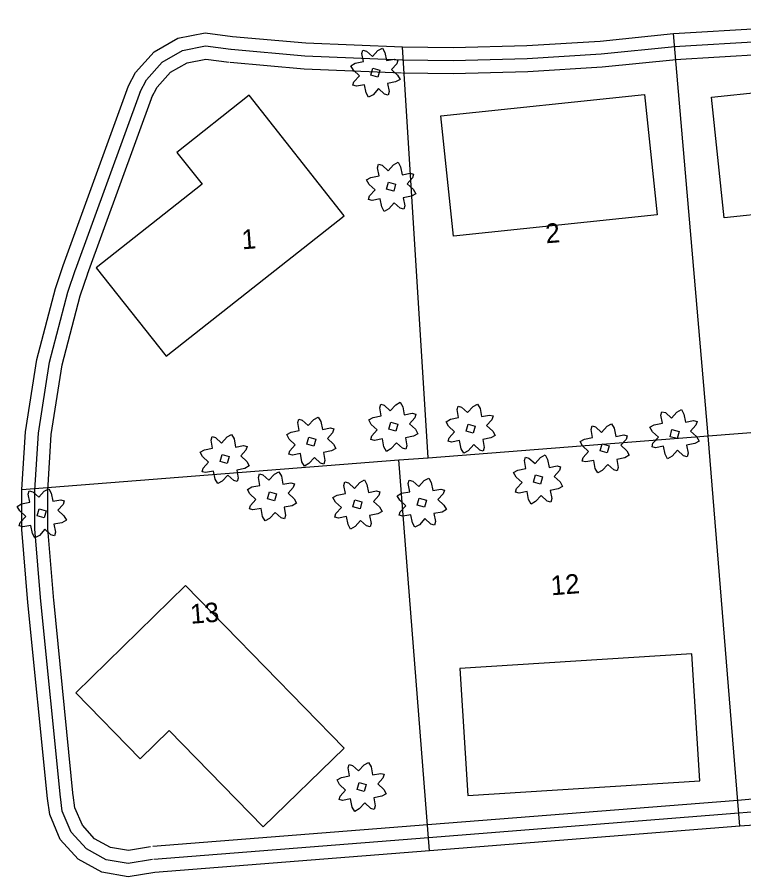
# Model space of a CAD drawing. Extents: x 1810019 to 1811399, y 1074962 to 1076105.
# Drawn here: x 1810018.7 to 1810242.7, y 1074961.5 to 1075226.6 of the extents above; entities that cross this region are included whole.
import ezdxf

# ---------------------------------------------------------------- set-up
doc = ezdxf.new("R2010")
doc.units = 0
for name, color, linetype in [('Environmental-New trees', 7, 'Continuous'), ('Property-Buildings', 7, 'Continuous'), ('Roadway-Land lines', 7, 'Continuous'), ('Roadway-Sidewalks', 7, 'Continuous'), ('Text-Property owner', 7, 'Continuous')]:
    doc.layers.add(name, color=color, linetype=linetype)

msp = doc.modelspace()

# ---------------------------------------------------------------- linework, layer by layer
at = {"layer": 'Environmental-New trees'}
for points in [[(1810122.18, 1075205.63), (1810122.48, 1075206.72), (1810124.18, 1075208.58), (1810122.32, 1075210.27), (1810121.54, 1075211.66), (1810122.89, 1075212.42), (1810125.4, 1075212.91), (1810124.92, 1075215.38), (1810125.23, 1075216.46), (1810126.31, 1075216.16), (1810128.17, 1075214.47), (1810129.87, 1075216.33), (1810131.26, 1075217.1), (1810132.03, 1075215.72), (1810132.51, 1075213.24), (1810134.98, 1075213.72), (1810136.06, 1075213.41), (1810135.69, 1075212.26), (1810134.06, 1075210.47), (1810135.92, 1075208.77), (1810136.7, 1075207.39), (1810135.35, 1075206.63), (1810132.84, 1075206.14), (1810133.31, 1075203.66), (1810133.01, 1075202.58), (1810131.93, 1075202.89), (1810130.06, 1075204.58), (1810128.37, 1075202.72), (1810126.98, 1075201.94), (1810126.21, 1075203.33), (1810125.73, 1075205.8), (1810123.26, 1075205.33)], [(1810128.34, 1075210.91), (1810130.51, 1075210.3), (1810129.9, 1075208.13), (1810127.73, 1075208.74)], [(1810127.02, 1075170.43), (1810127.33, 1075171.52), (1810129.02, 1075173.38), (1810127.16, 1075175.07), (1810126.38, 1075176.46), (1810127.73, 1075177.22), (1810130.24, 1075177.71), (1810129.77, 1075180.18), (1810130.07, 1075181.26), (1810131.16, 1075180.96), (1810133.02, 1075179.26), (1810134.71, 1075181.13), (1810136.1, 1075181.9), (1810136.88, 1075180.52), (1810137.35, 1075178.04), (1810139.82, 1075178.52), (1810140.9, 1075178.21), (1810140.53, 1075177.06), (1810138.9, 1075175.27), (1810140.77, 1075173.57), (1810141.54, 1075172.19), (1810140.19, 1075171.43), (1810137.68, 1075170.94), (1810138.16, 1075168.46), (1810137.85, 1075167.38), (1810136.77, 1075167.69), (1810134.91, 1075169.38), (1810133.21, 1075167.52), (1810131.83, 1075166.74), (1810131.05, 1075168.13), (1810130.57, 1075170.6), (1810128.1, 1075170.13)], [(1810133.18, 1075175.71), (1810135.35, 1075175.1), (1810134.74, 1075172.93), (1810132.57, 1075173.54)], [(1810127.69, 1075096.42), (1810128, 1075097.5), (1810129.69, 1075099.36), (1810127.83, 1075101.06), (1810127.05, 1075102.45), (1810128.4, 1075103.2), (1810130.91, 1075103.7), (1810130.44, 1075106.17), (1810130.74, 1075107.25), (1810131.83, 1075106.95), (1810133.69, 1075105.25), (1810135.38, 1075107.11), (1810136.77, 1075107.89), (1810137.55, 1075106.5), (1810138.02, 1075104.03), (1810140.49, 1075104.5), (1810141.58, 1075104.2), (1810141.21, 1075103.04), (1810139.58, 1075101.25), (1810141.44, 1075099.56), (1810142.22, 1075098.17), (1810140.86, 1075097.42), (1810138.36, 1075096.92), (1810138.83, 1075094.45), (1810138.52, 1075093.37), (1810137.44, 1075093.67), (1810135.58, 1075095.37), (1810133.89, 1075093.51), (1810132.5, 1075092.73), (1810131.72, 1075094.12), (1810131.25, 1075096.59), (1810128.78, 1075096.11)], [(1810151.52, 1075095.86), (1810151.82, 1075096.94), (1810153.52, 1075098.8), (1810151.66, 1075100.5), (1810150.88, 1075101.88), (1810152.23, 1075102.64), (1810154.74, 1075103.14), (1810154.27, 1075105.61), (1810154.57, 1075106.69), (1810155.65, 1075106.38), (1810157.51, 1075104.69), (1810159.21, 1075106.55), (1810160.6, 1075107.33), (1810161.37, 1075105.94), (1810161.85, 1075103.47), (1810164.32, 1075103.94), (1810165.4, 1075103.64), (1810165.03, 1075102.48), (1810163.4, 1075100.69), (1810165.26, 1075099), (1810166.04, 1075097.61), (1810164.69, 1075096.85), (1810162.18, 1075096.36), (1810162.65, 1075093.89), (1810162.35, 1075092.81), (1810161.27, 1075093.11), (1810159.41, 1075094.81), (1810157.71, 1075092.94), (1810156.32, 1075092.17), (1810155.55, 1075093.56), (1810155.07, 1075096.03), (1810152.6, 1075095.55)], [(1810214.38, 1075094.14), (1810214.68, 1075095.23), (1810216.38, 1075097.09), (1810214.52, 1075098.78), (1810213.74, 1075100.17), (1810215.09, 1075100.93), (1810217.6, 1075101.42), (1810217.13, 1075103.89), (1810217.43, 1075104.97), (1810218.51, 1075104.67), (1810220.37, 1075102.98), (1810222.07, 1075104.84), (1810223.46, 1075105.62), (1810224.23, 1075104.23), (1810224.71, 1075101.76), (1810227.18, 1075102.23), (1810228.26, 1075101.92), (1810227.89, 1075100.77), (1810226.26, 1075098.98), (1810228.12, 1075097.29), (1810228.9, 1075095.9), (1810227.55, 1075095.14), (1810225.04, 1075094.65), (1810225.51, 1075092.18), (1810225.21, 1075091.09), (1810224.13, 1075091.4), (1810222.27, 1075093.09), (1810220.57, 1075091.23), (1810219.18, 1075090.45), (1810218.41, 1075091.84), (1810217.93, 1075094.31), (1810215.46, 1075093.84)], [(1810102.42, 1075091.85), (1810102.73, 1075092.93), (1810104.42, 1075094.79), (1810102.56, 1075096.49), (1810101.78, 1075097.88), (1810103.13, 1075098.63), (1810105.64, 1075099.13), (1810105.17, 1075101.6), (1810105.47, 1075102.68), (1810106.56, 1075102.38), (1810108.42, 1075100.68), (1810110.11, 1075102.54), (1810111.5, 1075103.32), (1810112.28, 1075101.93), (1810112.75, 1075099.46), (1810115.22, 1075099.94), (1810116.3, 1075099.63), (1810115.93, 1075098.47), (1810114.31, 1075096.69), (1810116.17, 1075094.99), (1810116.94, 1075093.6), (1810115.59, 1075092.85), (1810113.08, 1075092.35), (1810113.56, 1075089.88), (1810113.25, 1075088.8), (1810112.17, 1075089.1), (1810110.31, 1075090.8), (1810108.61, 1075088.94), (1810107.23, 1075088.16), (1810106.45, 1075089.55), (1810105.98, 1075092.02), (1810103.5, 1075091.55)], [(1810133.86, 1075101.7), (1810136.02, 1075101.09), (1810135.41, 1075098.92), (1810133.25, 1075099.53)], [(1810157.68, 1075101.14), (1810159.85, 1075100.53), (1810159.24, 1075098.36), (1810157.07, 1075098.97)], [(1810192.85, 1075089.75), (1810193.15, 1075090.83), (1810194.85, 1075092.7), (1810192.98, 1075094.39), (1810192.21, 1075095.78), (1810193.56, 1075096.54), (1810196.07, 1075097.03), (1810195.59, 1075099.5), (1810195.9, 1075100.58), (1810196.98, 1075100.28), (1810198.84, 1075098.58), (1810200.54, 1075100.45), (1810201.92, 1075101.22), (1810202.7, 1075099.84), (1810203.18, 1075097.36), (1810205.65, 1075097.84), (1810206.73, 1075097.53), (1810206.36, 1075096.38), (1810204.73, 1075094.59), (1810206.59, 1075092.89), (1810207.37, 1075091.51), (1810206.02, 1075090.75), (1810203.51, 1075090.25), (1810203.98, 1075087.78), (1810203.68, 1075086.7), (1810202.59, 1075087.01), (1810200.73, 1075088.7), (1810199.04, 1075086.84), (1810197.65, 1075086.06), (1810196.87, 1075087.45), (1810196.4, 1075089.92), (1810193.93, 1075089.45)], [(1810220.54, 1075099.42), (1810222.71, 1075098.81), (1810222.1, 1075096.65), (1810219.93, 1075097.26)], [(1810075.69, 1075086.46), (1810075.99, 1075087.55), (1810077.69, 1075089.41), (1810075.83, 1075091.1), (1810075.05, 1075092.49), (1810076.4, 1075093.25), (1810078.91, 1075093.74), (1810078.44, 1075096.21), (1810078.74, 1075097.29), (1810079.82, 1075096.99), (1810081.68, 1075095.3), (1810083.38, 1075097.16), (1810084.77, 1075097.93), (1810085.54, 1075096.55), (1810086.02, 1075094.07), (1810088.49, 1075094.55), (1810089.57, 1075094.24), (1810089.2, 1075093.09), (1810087.57, 1075091.3), (1810089.43, 1075089.6), (1810090.21, 1075088.22), (1810088.86, 1075087.46), (1810086.35, 1075086.97), (1810086.83, 1075084.49), (1810086.52, 1075083.41), (1810085.44, 1075083.72), (1810083.58, 1075085.41), (1810081.88, 1075083.55), (1810080.49, 1075082.77), (1810079.72, 1075084.16), (1810079.24, 1075086.63), (1810076.77, 1075086.16)], [(1810108.58, 1075097.13), (1810110.75, 1075096.52), (1810110.14, 1075094.35), (1810107.97, 1075094.96)], [(1810199.01, 1075095.03), (1810201.18, 1075094.42), (1810200.57, 1075092.25), (1810198.4, 1075092.86)], [(1810081.85, 1075091.74), (1810084.02, 1075091.13), (1810083.41, 1075088.96), (1810081.24, 1075089.57)], [(1810172.31, 1075080.16), (1810172.61, 1075081.24), (1810174.31, 1075083.1), (1810172.45, 1075084.8), (1810171.67, 1075086.18), (1810173.02, 1075086.94), (1810175.53, 1075087.43), (1810175.06, 1075089.91), (1810175.36, 1075090.99), (1810176.44, 1075090.68), (1810178.31, 1075088.99), (1810180, 1075090.85), (1810181.39, 1075091.63), (1810182.16, 1075090.24), (1810182.64, 1075087.77), (1810185.11, 1075088.24), (1810186.19, 1075087.94), (1810185.82, 1075086.78), (1810184.19, 1075084.99), (1810186.05, 1075083.3), (1810186.83, 1075081.91), (1810185.48, 1075081.15), (1810182.97, 1075080.66), (1810183.45, 1075078.19), (1810183.14, 1075077.11), (1810182.06, 1075077.41), (1810180.2, 1075079.11), (1810178.5, 1075077.24), (1810177.11, 1075076.47), (1810176.34, 1075077.85), (1810175.86, 1075080.33), (1810173.39, 1075079.85)], [(1810090.28, 1075074.97), (1810090.59, 1075076.05), (1810092.28, 1075077.91), (1810090.42, 1075079.61), (1810089.64, 1075080.99), (1810091, 1075081.75), (1810093.5, 1075082.24), (1810093.03, 1075084.72), (1810093.34, 1075085.8), (1810094.42, 1075085.49), (1810096.28, 1075083.8), (1810097.97, 1075085.66), (1810099.36, 1075086.44), (1810100.14, 1075085.05), (1810100.61, 1075082.58), (1810103.08, 1075083.05), (1810104.17, 1075082.75), (1810103.8, 1075081.59), (1810102.17, 1075079.8), (1810104.03, 1075078.11), (1810104.81, 1075076.72), (1810103.46, 1075075.96), (1810100.95, 1075075.47), (1810101.42, 1075073), (1810101.12, 1075071.92), (1810100.03, 1075072.22), (1810098.17, 1075073.92), (1810096.48, 1075072.05), (1810095.09, 1075071.28), (1810094.31, 1075072.66), (1810093.84, 1075075.14), (1810091.37, 1075074.66)], [(1810116.64, 1075072.47), (1810116.94, 1075073.55), (1810118.64, 1075075.41), (1810116.78, 1075077.1), (1810116, 1075078.49), (1810117.35, 1075079.25), (1810119.86, 1075079.74), (1810119.39, 1075082.21), (1810119.69, 1075083.3), (1810120.77, 1075082.99), (1810122.63, 1075081.3), (1810124.33, 1075083.16), (1810125.72, 1075083.94), (1810126.49, 1075082.55), (1810126.97, 1075080.08), (1810129.44, 1075080.55), (1810130.52, 1075080.24), (1810130.15, 1075079.09), (1810128.52, 1075077.3), (1810130.38, 1075075.61), (1810131.16, 1075074.22), (1810129.81, 1075073.46), (1810127.3, 1075072.97), (1810127.77, 1075070.5), (1810127.47, 1075069.41), (1810126.39, 1075069.72), (1810124.53, 1075071.41), (1810122.83, 1075069.55), (1810121.44, 1075068.77), (1810120.67, 1075070.16), (1810120.19, 1075072.63), (1810117.72, 1075072.16)], [(1810136.48, 1075073.03), (1810136.78, 1075074.11), (1810138.48, 1075075.97), (1810136.61, 1075077.67), (1810135.84, 1075079.05), (1810137.19, 1075079.81), (1810139.7, 1075080.3), (1810139.22, 1075082.78), (1810139.53, 1075083.86), (1810140.61, 1075083.55), (1810142.47, 1075081.86), (1810144.17, 1075083.72), (1810145.55, 1075084.5), (1810146.33, 1075083.11), (1810146.8, 1075080.64), (1810149.28, 1075081.11), (1810150.36, 1075080.81), (1810149.99, 1075079.65), (1810148.36, 1075077.86), (1810150.22, 1075076.17), (1810151, 1075074.78), (1810149.65, 1075074.02), (1810147.14, 1075073.53), (1810147.61, 1075071.06), (1810147.31, 1075069.98), (1810146.22, 1075070.28), (1810144.36, 1075071.98), (1810142.67, 1075070.11), (1810141.28, 1075069.34), (1810140.5, 1075070.72), (1810140.03, 1075073.2), (1810137.56, 1075072.72)], [(1810178.47, 1075085.44), (1810180.64, 1075084.83), (1810180.03, 1075082.66), (1810177.86, 1075083.27)], [(1810019.32, 1075069.74), (1810019.62, 1075070.82), (1810021.32, 1075072.68), (1810019.46, 1075074.38), (1810018.68, 1075075.76), (1810020.03, 1075076.52), (1810022.54, 1075077.02), (1810022.07, 1075079.49), (1810022.37, 1075080.57), (1810023.45, 1075080.27), (1810025.31, 1075078.57), (1810027.01, 1075080.43), (1810028.4, 1075081.21), (1810029.17, 1075079.82), (1810029.65, 1075077.35), (1810032.12, 1075077.82), (1810033.2, 1075077.52), (1810032.83, 1075076.36), (1810031.2, 1075074.57), (1810033.06, 1075072.88), (1810033.84, 1075071.49), (1810032.49, 1075070.74), (1810029.98, 1075070.24), (1810030.45, 1075067.77), (1810030.15, 1075066.69), (1810029.07, 1075066.99), (1810027.21, 1075068.69), (1810025.51, 1075066.83), (1810024.12, 1075066.05), (1810023.35, 1075067.44), (1810022.87, 1075069.91), (1810020.4, 1075069.43)], [(1810096.45, 1075080.25), (1810098.61, 1075079.64), (1810098, 1075077.47), (1810095.84, 1075078.08)], [(1810122.8, 1075077.74), (1810124.97, 1075077.13), (1810124.36, 1075074.97), (1810122.19, 1075075.58)], [(1810142.64, 1075078.31), (1810144.81, 1075077.7), (1810144.2, 1075075.53), (1810142.03, 1075076.14)], [(1810025.48, 1075075.02), (1810027.65, 1075074.41), (1810027.04, 1075072.24), (1810024.87, 1075072.85)], [(1810117.93, 1074985.36), (1810118.23, 1074986.44), (1810119.93, 1074988.3), (1810118.06, 1074990), (1810117.29, 1074991.39), (1810118.64, 1074992.14), (1810121.15, 1074992.64), (1810120.67, 1074995.11), (1810120.98, 1074996.19), (1810122.06, 1074995.89), (1810123.92, 1074994.19), (1810125.62, 1074996.05), (1810127, 1074996.83), (1810127.78, 1074995.44), (1810128.26, 1074992.97), (1810130.73, 1074993.44), (1810131.81, 1074993.14), (1810131.44, 1074991.98), (1810129.81, 1074990.19), (1810131.67, 1074988.5), (1810132.45, 1074987.11), (1810131.1, 1074986.36), (1810128.59, 1074985.86), (1810129.06, 1074983.39), (1810128.76, 1074982.31), (1810127.68, 1074982.61), (1810125.81, 1074984.31), (1810124.12, 1074982.45), (1810122.73, 1074981.67), (1810121.95, 1074983.06), (1810121.48, 1074985.53), (1810119.01, 1074985.05)], [(1810124.09, 1074990.64), (1810126.26, 1074990.03), (1810125.65, 1074987.86), (1810123.48, 1074988.47)]]:
    msp.add_lwpolyline(points, close=True, dxfattribs=at)
at = {"layer": 'Property-Buildings'}
for points in [[(1810232.74, 1075201.92), (1810295.57, 1075208.5), (1810299.46, 1075171.37), (1810236.63, 1075164.79)], [(1810064.6, 1075122.04), (1810119.5, 1075165.36), (1810090.18, 1075202.53), (1810067.88, 1075184.93), (1810075.65, 1075175.09), (1810043.04, 1075149.36)], [(1810149.28, 1075196.19), (1810212.11, 1075202.77), (1810216, 1075165.65), (1810153.17, 1075159.06)], [(1810119.44, 1075001.25), (1810070.61, 1075051.32), (1810036.71, 1075018.26), (1810056.54, 1074997.93), (1810065.52, 1075006.68), (1810094.52, 1074976.95)], [(1810157.61, 1074986.59), (1810229.12, 1074991.12), (1810226.63, 1075030.3), (1810155.12, 1075025.76)]]:
    msp.add_lwpolyline(points, close=True, dxfattribs=at)
at = {"layer": 'Roadway-Land lines'}
for p, q in [((1810220.99, 1075221.55), (1810306.17, 1075226.61)), ((1810231.65, 1075097.52), (1810220.99, 1075221.55)), ((1810145.37, 1075090.78), (1810137.51, 1075217.47)), ((1810032.85, 1075150.09), (1810053, 1075205.4)), ((1810231.65, 1075097.52), (1810315.51, 1075104.07)), ((1810145.37, 1075090.78), (1810231.65, 1075097.52)), ((1810241.42, 1074977.13), (1810231.65, 1075097.52)), ((1810020.12, 1075081.01), (1810136.35, 1075090.08)), ((1810136.35, 1075090.08), (1810145.37, 1075090.78)), ((1810145.76, 1074969.58), (1810136.35, 1075090.08)), ((1810028.02, 1074985.66), (1810022, 1075046.13)), ((1810328.22, 1074983.99), (1810241.42, 1074977.13)), ((1810241.42, 1074977.13), (1810145.76, 1074969.58)), ((1810145.76, 1074969.58), (1810061.09, 1074962.89))]:
    msp.add_line(p, q, dxfattribs=at)
for points in [[(1810053, 1075205.4), (1810055.19, 1075209.6), (1810060.86, 1075215.93), (1810068.25, 1075220.14), (1810076.59, 1075221.79), (1810085.03, 1075220.71)], [(1810137.51, 1075217.47), (1810153.03, 1075217.28), (1810175.74, 1075217.84), (1810198.4, 1075219.27), (1810220.99, 1075221.55)], [(1810085.03, 1075220.71), (1810107.65, 1075218.71), (1810137.51, 1075217.47)], [(1810020.12, 1075081.01), (1810021.22, 1075098.76), (1810024.71, 1075121.09), (1810030.45, 1075142.95), (1810032.85, 1075150.09)], [(1810022, 1075046.13), (1810020.14, 1075068.65), (1810020.12, 1075081.01)], [(1810061.09, 1074962.89), (1810052.91, 1074961.53), (1810044.74, 1074962.93), (1810037.48, 1074966.93), (1810031.92, 1074973.08), (1810028.69, 1074980.71), (1810028.02, 1074985.66)]]:
    msp.add_lwpolyline(points, dxfattribs=at)
at = {"layer": 'Roadway-Sidewalks'}
for p, q in [((1810221.23, 1075217.56), (1810306.41, 1075222.62)), ((1810221.47, 1075213.56), (1810306.65, 1075218.63)), ((1810036.61, 1075148.72), (1810056.76, 1075204.03)), ((1810040.37, 1075147.35), (1810060.51, 1075202.66)), ((1810032, 1074986.05), (1810025.98, 1075046.52)), ((1810035.98, 1074986.45), (1810029.97, 1075046.92)), ((1810327.59, 1074991.96), (1810240.79, 1074985.11)), ((1810327.91, 1074987.98), (1810241.1, 1074981.12)), ((1810240.79, 1074985.11), (1810145.13, 1074977.55)), ((1810241.1, 1074981.12), (1810145.44, 1074973.56)), ((1810145.13, 1074977.55), (1810060.46, 1074970.86)), ((1810145.44, 1074973.56), (1810060.78, 1074966.88))]:
    msp.add_line(p, q, dxfattribs=at)
for points in [[(1810056.54, 1075203.55), (1810058.5, 1075207.31), (1810063.41, 1075212.78), (1810069.67, 1075216.34), (1810076.73, 1075217.74), (1810084.52, 1075216.75)], [(1810084.67, 1075216.73), (1810107.39, 1075214.72), (1810137.35, 1075213.48)], [(1810137.46, 1075213.47), (1810153.06, 1075213.27), (1810175.91, 1075213.85), (1810198.73, 1075215.28), (1810221.4, 1075217.57)], [(1810060.09, 1075201.7), (1810061.82, 1075205.01), (1810065.95, 1075209.62), (1810071.08, 1075212.54), (1810076.87, 1075213.69), (1810084.01, 1075212.78)], [(1810137.41, 1075209.47), (1810153.08, 1075209.27), (1810176.09, 1075209.85), (1810199.05, 1075211.29), (1810221.8, 1075213.59)], [(1810084.32, 1075212.74), (1810107.13, 1075210.73), (1810137.18, 1075209.48)], [(1810024.11, 1075080.76), (1810025.2, 1075098.32), (1810028.63, 1075120.27), (1810034.28, 1075141.8), (1810036.65, 1075148.81)], [(1810028.1, 1075080.51), (1810029.18, 1075097.89), (1810032.55, 1075119.45), (1810038.12, 1075140.65), (1810040.44, 1075147.54)], [(1810025.99, 1075046.46), (1810024.14, 1075068.82), (1810024.12, 1075081.01)], [(1810029.98, 1075046.79), (1810028.14, 1075068.99), (1810028.12, 1075081.02)], [(1810060.44, 1074966.83), (1810052.92, 1074965.59), (1810046.08, 1074966.76), (1810040, 1074970.11), (1810035.34, 1074975.26), (1810032.58, 1074981.78), (1810031.98, 1074986.19)], [(1810059.79, 1074970.78), (1810052.94, 1074969.65), (1810047.42, 1074970.59), (1810042.51, 1074973.29), (1810038.76, 1074977.44), (1810036.47, 1074982.85), (1810035.94, 1074986.73)]]:
    msp.add_lwpolyline(points, dxfattribs=at)

# ---------------------------------------------------------------- texts
at = {"layer": 'Text-Property owner'}
for s, p in [('2', (1810181.75, 1075156.88)), ('1', (1810088.07, 1075155.01)), ('12', (1810183.38, 1075048.32)), ('13', (1810072.22, 1075039.55))]:
    msp.add_text(s, height=6, rotation=4.4642, dxfattribs=at).set_placement(p)

doc.saveas('drawing.dxf')
